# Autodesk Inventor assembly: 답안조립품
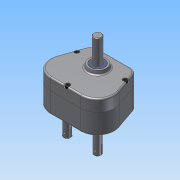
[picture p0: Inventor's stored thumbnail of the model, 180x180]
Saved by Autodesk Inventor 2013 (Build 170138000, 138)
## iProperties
Created: 2014-12
Part Number: 답안조립품
Document SubType Name: Assembly
Designer: WINDOWS7
Author: WINDOWS7
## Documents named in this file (14)
- C:\Users\WINDOWS7\Desktop\441209V1037\답안조립품.iam
- C:\Users\WINDOWS7\Desktop\441209V1037\본체.ipt
- C:\Users\WINDOWS7\Desktop\441209V1037\커버.ipt
- C:\Users\WINDOWS7\Desktop\441209V1037\M 5 x 35.ipt
- C:\Users\WINDOWS7\Desktop\441209V1037\베어링- 6203.ipt
- C:\Users\WINDOWS7\Desktop\441209V1037\베어링- 6202.ipt
- C:\Users\WINDOWS7\Desktop\441209V1037\메인축.ipt
- C:\Users\WINDOWS7\Desktop\441209V1037\키5x5.ipt
- C:\Users\WINDOWS7\Desktop\441209V1037\메인기어.ipt
- C:\Users\WINDOWS7\Desktop\441209V1037\멈춤링.ipt
- C:\Users\WINDOWS7\Desktop\441209V1037\서브축.ipt
- C:\Users\WINDOWS7\Desktop\441209V1037\서브기어.ipt
- C:\Users\WINDOWS7\Desktop\441209V1037\오일시일-D-17.ipt
- C:\Users\WINDOWS7\Desktop\441209V1037\오일시일-D-15.ipt
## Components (15 placed, 6 different names)
1. KS B 1003 - 미터 M 5 x 35:1
2. KS B 1003 - 미터 M 5 x 35:2
3. KS B 1003 - 미터 M 5 x 35:3
4. KS B 2023 6203 - 17 x 40 x 12:1
5. KS B 2023 6202 - 15 x 35 x 11:1
6. KS B 2023 6202 - 15 x 35 x 11:2
7. KS B 2023 6203 - 17 x 40 x 12:2
8. KS B 2023 6203 - 17 x 40 x 12:3
9. KS B 2023 6203 - 17 x 40 x 12:4
10. KS B 1336 17 x 1:1
11. KS B 1336 17 x 1:2
12. KS B 1336 17 x 1:3
13. KS B 2804 D D - 17 30 8:1
14. KS B 2804 D D - 15 30 7:1
15. KS B 2804 D D - 15 30 7:2
